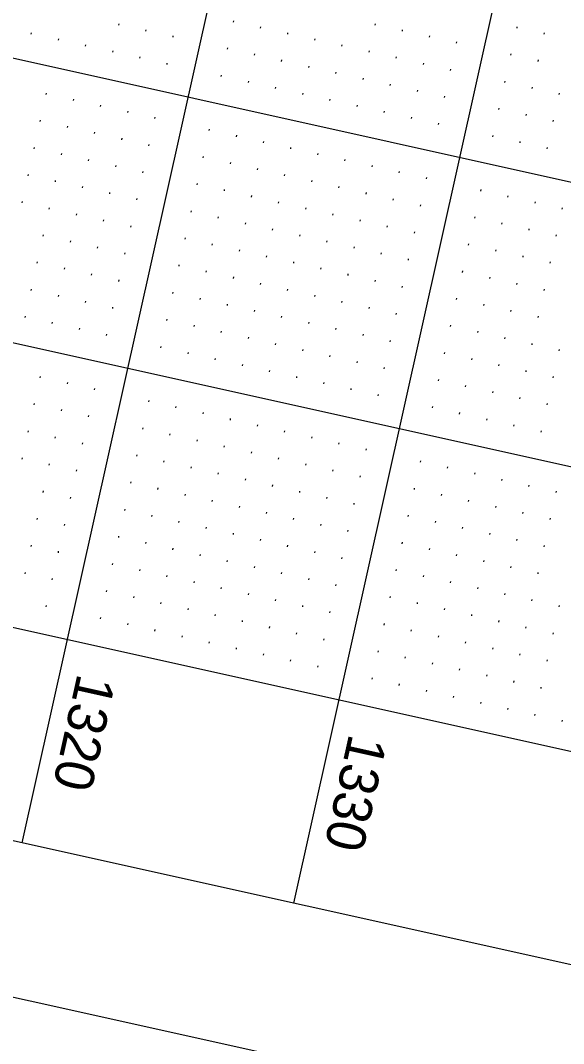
# Model space of a CAD drawing. Extents: x 2149268 to 2150830, y 142155 to 144285.
# Drawn here: x 2149718.3 to 2149815.9, y 142325.7 to 142509.8 of the extents above; entities that cross this region are included whole.
import ezdxf

# ---------------------------------------------------------------- set-up
doc = ezdxf.new("R2010")
doc.units = 0
for name, color, linetype in [('SHT_Plan_Profile_Sheet_Elev_Txt', 7, 'Continuous'), ('SHT_Plot_Shape_Half', 7, 'Continuous'), ('SHT_Profile_Grid_Major', 7, 'Continuous'), ('SHT_Profile_Grid_Minor', 7, 'Continuous'), ('SHT_Sheet_Border', 7, 'Continuous')]:
    doc.layers.add(name, color=color, linetype=linetype)

msp = doc.modelspace()

# ---------------------------------------------------------------- linework, layer by layer
at = {"layer": 'SHT_Plot_Shape_Half'}
msp.add_lwpolyline([(2150772.24, 143840.86), (2150403.25, 142181.39), (2149329.47, 142420.15), (2149698.47, 144079.62)], close=True, dxfattribs=at)
at = {"layer": 'SHT_Profile_Grid_Major'}
for p, q in [((2150060.45, 143899.25), (2149718.58, 142361.8)), ((2150109.25, 143888.4), (2149767.39, 142350.95)), ((2149504.39, 142550.29), (2149894.85, 142463.47)), ((2149493.54, 142501.48), (2149884, 142414.66))]:
    msp.add_line(p, q, dxfattribs=at)
at = {"layer": 'SHT_Profile_Grid_Minor'}
for p, q in [((2149735.98, 142509.16), (2149735.93, 142508.92)), ((2149740.86, 142508.08), (2149740.81, 142507.84)), ((2149756.59, 142509.7), (2149756.54, 142509.46)), ((2149761.47, 142508.62), (2149761.42, 142508.37)), ((2149782.08, 142509.16), (2149782.03, 142508.91)), ((2149786.96, 142508.07), (2149786.91, 142507.83)), ((2149807.57, 142508.61), (2149807.52, 142508.37)), ((2149720.26, 142507.54), (2149720.2, 142507.3)), ((2149725.14, 142506.45), (2149725.08, 142506.21)), ((2149745.74, 142506.99), (2149745.69, 142506.75)), ((2149766.35, 142507.53), (2149766.3, 142507.29)), ((2149771.23, 142506.45), (2149771.18, 142506.2)), ((2149791.84, 142506.99), (2149791.79, 142506.74)), ((2149812.45, 142507.53), (2149812.4, 142507.28)), ((2149730.02, 142505.37), (2149729.96, 142505.13)), ((2149734.9, 142504.28), (2149734.84, 142504.04)), ((2149755.51, 142504.82), (2149755.45, 142504.58)), ((2149776.12, 142505.36), (2149776.06, 142505.12)), ((2149781, 142504.28), (2149780.94, 142504.03)), ((2149796.72, 142505.9), (2149796.67, 142505.66)), ((2149739.78, 142503.2), (2149739.72, 142502.95)), ((2149760.39, 142503.74), (2149760.33, 142503.49)), ((2149765.27, 142502.65), (2149765.21, 142502.41)), ((2149785.88, 142503.19), (2149785.82, 142502.95)), ((2149806.49, 142503.73), (2149806.43, 142503.49)), ((2149811.37, 142502.65), (2149811.31, 142502.4)), ((2149744.66, 142502.11), (2149744.61, 142501.87)), ((2149770.15, 142501.57), (2149770.09, 142501.32)), ((2149790.76, 142502.11), (2149790.7, 142501.86)), ((2149795.64, 142501.02), (2149795.58, 142500.78)), ((2149754.42, 142499.94), (2149754.37, 142499.7)), ((2149759.3, 142498.86), (2149759.25, 142498.61)), ((2149775.03, 142500.48), (2149774.98, 142500.24)), ((2149779.91, 142499.4), (2149779.86, 142499.15)), ((2149805.4, 142498.85), (2149805.35, 142498.61)), ((2149764.18, 142497.77), (2149764.13, 142497.53)), ((2149784.79, 142498.31), (2149784.74, 142498.07)), ((2149789.67, 142497.23), (2149789.62, 142496.98)), ((2149810.28, 142497.77), (2149810.23, 142497.52)), ((2149722.97, 142496.69), (2149722.91, 142496.45)), ((2149727.85, 142495.61), (2149727.79, 142495.36)), ((2149769.06, 142496.69), (2149769.01, 142496.44)), ((2149773.94, 142495.6), (2149773.89, 142495.36)), ((2149794.55, 142496.14), (2149794.5, 142495.9)), ((2149815.16, 142496.68), (2149815.11, 142496.44)), ((2149732.73, 142494.52), (2149732.67, 142494.28)), ((2149737.61, 142493.44), (2149737.55, 142493.19)), ((2149778.83, 142494.52), (2149778.77, 142494.27)), ((2149783.71, 142493.43), (2149783.65, 142493.19)), ((2149804.31, 142493.97), (2149804.26, 142493.73)), ((2149721.88, 142491.81), (2149721.83, 142491.57)), ((2149742.49, 142492.35), (2149742.43, 142492.11)), ((2149788.59, 142492.35), (2149788.53, 142492.1)), ((2149809.2, 142492.89), (2149809.14, 142492.64)), ((2149814.08, 142491.8), (2149814.02, 142491.56)), ((2149726.76, 142490.73), (2149726.71, 142490.48)), ((2149731.64, 142489.64), (2149731.59, 142489.4)), ((2149752.25, 142490.18), (2149752.2, 142489.94)), ((2149793.47, 142491.26), (2149793.41, 142491.02)), ((2149736.52, 142488.56), (2149736.47, 142488.31)), ((2149757.13, 142489.1), (2149757.08, 142488.85)), ((2149762.01, 142488.01), (2149761.96, 142487.77)), ((2149803.23, 142489.09), (2149803.18, 142488.85)), ((2149808.11, 142488), (2149808.06, 142487.76)), ((2149720.8, 142486.93), (2149720.74, 142486.69)), ((2149725.68, 142485.85), (2149725.62, 142485.6)), ((2149741.4, 142487.47), (2149741.35, 142487.23)), ((2149766.89, 142486.93), (2149766.84, 142486.68)), ((2149771.77, 142485.84), (2149771.72, 142485.6)), ((2149812.99, 142486.92), (2149812.94, 142486.68)), ((2149730.56, 142484.76), (2149730.5, 142484.52)), ((2149751.17, 142485.3), (2149751.11, 142485.06)), ((2149756.05, 142484.21), (2149755.99, 142483.97)), ((2149776.65, 142484.75), (2149776.6, 142484.51)), ((2149735.44, 142483.68), (2149735.38, 142483.43)), ((2149740.32, 142482.59), (2149740.26, 142482.35)), ((2149760.93, 142483.13), (2149760.87, 142482.89)), ((2149781.54, 142483.67), (2149781.48, 142483.43)), ((2149786.42, 142482.58), (2149786.36, 142482.34)), ((2149719.71, 142482.05), (2149719.66, 142481.81)), ((2149724.59, 142480.97), (2149724.54, 142480.72)), ((2149750.08, 142480.42), (2149750.03, 142480.18)), ((2149765.81, 142482.04), (2149765.75, 142481.8)), ((2149770.69, 142480.96), (2149770.63, 142480.72)), ((2149791.3, 142481.5), (2149791.24, 142481.25)), ((2149729.47, 142479.88), (2149729.42, 142479.64)), ((2149734.35, 142478.79), (2149734.3, 142478.55)), ((2149754.96, 142479.33), (2149754.91, 142479.09)), ((2149775.57, 142479.87), (2149775.52, 142479.63)), ((2149780.45, 142478.79), (2149780.4, 142478.54)), ((2149801.06, 142479.33), (2149801, 142479.08)), ((2149718.62, 142477.17), (2149718.57, 142476.93)), ((2149739.23, 142477.71), (2149739.18, 142477.47)), ((2149759.84, 142478.25), (2149759.79, 142478)), ((2149764.72, 142477.16), (2149764.67, 142476.92)), ((2149785.33, 142477.7), (2149785.28, 142477.46)), ((2149805.94, 142478.24), (2149805.89, 142478)), ((2149810.82, 142477.16), (2149810.77, 142476.91)), ((2149723.51, 142476.08), (2149723.45, 142475.84)), ((2149728.39, 142475), (2149728.33, 142474.75)), ((2149748.99, 142475.54), (2149748.94, 142475.29)), ((2149769.6, 142476.08), (2149769.55, 142475.83)), ((2149774.48, 142474.99), (2149774.43, 142474.75)), ((2149790.21, 142476.62), (2149790.16, 142476.37)), ((2149815.7, 142476.07), (2149815.65, 142475.83)), ((2149733.27, 142473.91), (2149733.21, 142473.67)), ((2149753.88, 142474.45), (2149753.82, 142474.21)), ((2149758.76, 142473.37), (2149758.7, 142473.12)), ((2149779.36, 142473.91), (2149779.31, 142473.66)), ((2149799.97, 142474.45), (2149799.92, 142474.2)), ((2149804.85, 142473.36), (2149804.8, 142473.12)), ((2149722.42, 142471.2), (2149722.37, 142470.96)), ((2149738.15, 142472.83), (2149738.09, 142472.58)), ((2149763.64, 142472.28), (2149763.58, 142472.04)), ((2149768.52, 142471.2), (2149768.46, 142470.95)), ((2149784.25, 142472.82), (2149784.19, 142472.58)), ((2149789.13, 142471.74), (2149789.07, 142471.49)), ((2149809.73, 142472.28), (2149809.68, 142472.03)), ((2149814.62, 142471.19), (2149814.56, 142470.95)), ((2149727.3, 142470.12), (2149727.25, 142469.87)), ((2149747.91, 142470.66), (2149747.86, 142470.41)), ((2149752.79, 142469.57), (2149752.74, 142469.33)), ((2149773.4, 142470.11), (2149773.34, 142469.87)), ((2149798.89, 142469.57), (2149798.83, 142469.32)), ((2149732.18, 142469.03), (2149732.13, 142468.79)), ((2149737.06, 142467.95), (2149737.01, 142467.7)), ((2149757.67, 142468.49), (2149757.62, 142468.24)), ((2149778.28, 142469.03), (2149778.23, 142468.78)), ((2149783.16, 142467.94), (2149783.11, 142467.7)), ((2149803.77, 142468.48), (2149803.71, 142468.24)), ((2149721.34, 142466.32), (2149721.28, 142466.08)), ((2149746.82, 142465.78), (2149746.77, 142465.53)), ((2149762.55, 142467.4), (2149762.5, 142467.16)), ((2149767.43, 142466.32), (2149767.38, 142466.07)), ((2149788.04, 142466.86), (2149787.99, 142466.61)), ((2149808.65, 142467.4), (2149808.6, 142467.15)), ((2149813.53, 142466.31), (2149813.48, 142466.07)), ((2149726.22, 142465.24), (2149726.16, 142464.99)), ((2149731.1, 142464.15), (2149731.04, 142463.91)), ((2149751.71, 142464.69), (2149751.65, 142464.45)), ((2149772.31, 142465.23), (2149772.26, 142464.99)), ((2149777.19, 142464.15), (2149777.14, 142463.9)), ((2149797.8, 142464.69), (2149797.75, 142464.44)), ((2149735.98, 142463.07), (2149735.92, 142462.82)), ((2149756.59, 142463.61), (2149756.53, 142463.36)), ((2149761.47, 142462.52), (2149761.41, 142462.28)), ((2149782.08, 142463.06), (2149782.02, 142462.82)), ((2149786.96, 142461.98), (2149786.9, 142461.73)), ((2149802.68, 142463.6), (2149802.63, 142463.36)), ((2149807.56, 142462.52), (2149807.51, 142462.27)), ((2149720.25, 142461.44), (2149720.2, 142461.2)), ((2149725.13, 142460.36), (2149725.08, 142460.11)), ((2149745.74, 142460.9), (2149745.68, 142460.65)), ((2149766.35, 142461.44), (2149766.29, 142461.19)), ((2149771.23, 142460.35), (2149771.17, 142460.11)), ((2149812.45, 142461.43), (2149812.39, 142461.19)), ((2149730.01, 142459.27), (2149729.96, 142459.03)), ((2149750.62, 142459.81), (2149750.57, 142459.57)), ((2149755.5, 142458.73), (2149755.45, 142458.48)), ((2149776.11, 142459.27), (2149776.05, 142459.02)), ((2149796.72, 142459.81), (2149796.66, 142459.56)), ((2149801.6, 142458.72), (2149801.54, 142458.48)), ((2149719.16, 142456.56), (2149719.11, 142456.32)), ((2149734.89, 142458.19), (2149734.84, 142457.94)), ((2149760.38, 142457.64), (2149760.33, 142457.4)), ((2149765.26, 142456.56), (2149765.21, 142456.31)), ((2149780.99, 142458.18), (2149780.94, 142457.94)), ((2149785.87, 142457.09), (2149785.82, 142456.85)), ((2149806.48, 142457.63), (2149806.42, 142457.39)), ((2149811.36, 142456.55), (2149811.31, 142456.31)), ((2149724.05, 142455.48), (2149723.99, 142455.23)), ((2149744.65, 142456.02), (2149744.6, 142455.77)), ((2149749.53, 142454.93), (2149749.48, 142454.69)), ((2149770.14, 142455.47), (2149770.09, 142455.23)), ((2149795.63, 142454.92), (2149795.58, 142454.68)), ((2149728.93, 142454.39), (2149728.87, 142454.15)), ((2149733.81, 142453.31), (2149733.75, 142453.06)), ((2149754.42, 142453.84), (2149754.36, 142453.6)), ((2149759.3, 142452.76), (2149759.24, 142452.52)), ((2149775.02, 142454.38), (2149774.97, 142454.14)), ((2149779.9, 142453.3), (2149779.85, 142453.06)), ((2149800.51, 142453.84), (2149800.46, 142453.6)), ((2149805.39, 142452.75), (2149805.34, 142452.51)), ((2149743.57, 142451.13), (2149743.51, 142450.89)), ((2149764.18, 142451.67), (2149764.12, 142451.43)), ((2149784.79, 142452.21), (2149784.73, 142451.97)), ((2149810.27, 142451.67), (2149810.22, 142451.42)), ((2149748.45, 142450.05), (2149748.4, 142449.81)), ((2149769.06, 142450.59), (2149769, 142450.35)), ((2149773.94, 142449.5), (2149773.88, 142449.26)), ((2149794.55, 142450.04), (2149794.49, 142449.8)), ((2149815.16, 142450.58), (2149815.1, 142450.34)), ((2149753.33, 142448.96), (2149753.28, 142448.72)), ((2149758.21, 142447.88), (2149758.16, 142447.63)), ((2149778.82, 142448.42), (2149778.77, 142448.17)), ((2149783.7, 142447.33), (2149783.65, 142447.09)), ((2149799.43, 142448.96), (2149799.37, 142448.71)), ((2149804.31, 142447.87), (2149804.25, 142447.63)), ((2149721.87, 142445.71), (2149721.82, 142445.47)), ((2149763.09, 142446.79), (2149763.04, 142446.55)), ((2149767.97, 142445.71), (2149767.92, 142445.46)), ((2149809.19, 142446.79), (2149809.14, 142446.54)), ((2149814.07, 142445.7), (2149814.02, 142445.46)), ((2149726.76, 142444.63), (2149726.7, 142444.38)), ((2149731.64, 142443.54), (2149731.58, 142443.3)), ((2149772.85, 142444.62), (2149772.8, 142444.38)), ((2149777.73, 142443.54), (2149777.68, 142443.29)), ((2149793.46, 142445.16), (2149793.41, 142444.92)), ((2149798.34, 142444.08), (2149798.29, 142443.83)), ((2149782.61, 142442.45), (2149782.56, 142442.21)), ((2149803.22, 142442.99), (2149803.17, 142442.75)), ((2149808.1, 142441.91), (2149808.05, 142441.66)), ((2149720.79, 142440.83), (2149720.74, 142440.59)), ((2149741.4, 142441.37), (2149741.34, 142441.13)), ((2149746.28, 142440.29), (2149746.22, 142440.04)), ((2149792.38, 142440.28), (2149792.32, 142440.04)), ((2149812.98, 142440.82), (2149812.93, 142440.58)), ((2149725.67, 142439.75), (2149725.62, 142439.5)), ((2149730.55, 142438.66), (2149730.5, 142438.42)), ((2149751.16, 142439.2), (2149751.11, 142438.96)), ((2149756.04, 142438.12), (2149755.99, 142437.87)), ((2149797.26, 142439.2), (2149797.2, 142438.95)), ((2149802.14, 142438.11), (2149802.08, 142437.87)), ((2149740.31, 142436.49), (2149740.26, 142436.25)), ((2149760.92, 142437.03), (2149760.87, 142436.79)), ((2149807.02, 142437.03), (2149806.96, 142436.78)), ((2149719.7, 142435.95), (2149719.65, 142435.71)), ((2149724.58, 142434.87), (2149724.53, 142434.62)), ((2149745.19, 142435.41), (2149745.14, 142435.16)), ((2149750.07, 142434.32), (2149750.02, 142434.08)), ((2149765.8, 142435.95), (2149765.75, 142435.7)), ((2149770.68, 142434.86), (2149770.63, 142434.62)), ((2149811.9, 142435.94), (2149811.85, 142435.7)), ((2149729.47, 142433.78), (2149729.41, 142433.54)), ((2149754.96, 142433.24), (2149754.9, 142432.99)), ((2149775.56, 142433.78), (2149775.51, 142433.53)), ((2149780.44, 142432.69), (2149780.39, 142432.45)), ((2149718.62, 142431.07), (2149718.56, 142430.83)), ((2149739.23, 142431.61), (2149739.17, 142431.37)), ((2149759.84, 142432.15), (2149759.78, 142431.91)), ((2149764.72, 142431.07), (2149764.66, 142430.82)), ((2149723.5, 142429.99), (2149723.45, 142429.74)), ((2149728.38, 142428.9), (2149728.33, 142428.66)), ((2149744.11, 142430.53), (2149744.05, 142430.28)), ((2149748.99, 142429.44), (2149748.93, 142429.2)), ((2149769.6, 142429.98), (2149769.54, 142429.74)), ((2149774.48, 142428.9), (2149774.42, 142428.65)), ((2149790.21, 142430.52), (2149790.15, 142430.28)), ((2149795.09, 142429.44), (2149795.03, 142429.19)), ((2149753.87, 142428.36), (2149753.82, 142428.11)), ((2149758.75, 142427.27), (2149758.7, 142427.03)), ((2149779.36, 142427.81), (2149779.3, 142427.57)), ((2149799.97, 142428.35), (2149799.91, 142428.11)), ((2149804.85, 142427.26), (2149804.79, 142427.02)), ((2149722.41, 142425.11), (2149722.36, 142424.86)), ((2149738.14, 142426.73), (2149738.09, 142426.49)), ((2149743.02, 142425.65), (2149742.97, 142425.4)), ((2149763.63, 142426.19), (2149763.58, 142425.94)), ((2149768.51, 142425.1), (2149768.46, 142424.86)), ((2149789.12, 142425.64), (2149789.07, 142425.4)), ((2149809.73, 142426.18), (2149809.67, 142425.94)), ((2149727.3, 142424.02), (2149727.24, 142423.78)), ((2149747.9, 142424.56), (2149747.85, 142424.32)), ((2149752.78, 142423.47), (2149752.73, 142423.23)), ((2149773.39, 142424.01), (2149773.34, 142423.77)), ((2149794, 142424.55), (2149793.95, 142424.31)), ((2149798.88, 142423.47), (2149798.83, 142423.22)), ((2149814.61, 142425.09), (2149814.56, 142424.85)), ((2149737.06, 142421.85), (2149737, 142421.61)), ((2149757.67, 142422.39), (2149757.61, 142422.15)), ((2149778.27, 142422.93), (2149778.22, 142422.69)), ((2149803.76, 142422.38), (2149803.71, 142422.14)), ((2149721.33, 142420.23), (2149721.27, 142419.98)), ((2149741.94, 142420.76), (2149741.88, 142420.52)), ((2149746.82, 142419.68), (2149746.76, 142419.44)), ((2149762.55, 142421.3), (2149762.49, 142421.06)), ((2149767.43, 142420.22), (2149767.37, 142419.98)), ((2149788.04, 142420.76), (2149787.98, 142420.51)), ((2149792.92, 142419.67), (2149792.86, 142419.43)), ((2149808.64, 142421.3), (2149808.59, 142421.05)), ((2149813.52, 142420.21), (2149813.47, 142419.97)), ((2149726.21, 142419.14), (2149726.16, 142418.9)), ((2149751.7, 142418.59), (2149751.64, 142418.35)), ((2149772.31, 142419.13), (2149772.25, 142418.89)), ((2149777.19, 142418.05), (2149777.13, 142417.8)), ((2149797.8, 142418.59), (2149797.74, 142418.34)), ((2149735.97, 142416.97), (2149735.92, 142416.73)), ((2149756.58, 142417.51), (2149756.53, 142417.26)), ((2149761.46, 142416.42), (2149761.41, 142416.18)), ((2149802.68, 142417.5), (2149802.62, 142417.26)), ((2149807.56, 142416.42), (2149807.5, 142416.17)), ((2149720.24, 142415.34), (2149720.19, 142415.1)), ((2149725.12, 142414.26), (2149725.07, 142414.01)), ((2149740.85, 142415.88), (2149740.8, 142415.64)), ((2149745.73, 142414.8), (2149745.68, 142414.55)), ((2149766.34, 142415.34), (2149766.29, 142415.09)), ((2149771.22, 142414.25), (2149771.17, 142414.01)), ((2149786.95, 142415.88), (2149786.9, 142415.63)), ((2149791.83, 142414.79), (2149791.78, 142414.55)), ((2149812.44, 142415.33), (2149812.39, 142415.09)), ((2149750.61, 142413.71), (2149750.56, 142413.47)), ((2149755.49, 142412.63), (2149755.44, 142412.38)), ((2149776.1, 142413.17), (2149776.05, 142412.92)), ((2149796.71, 142413.71), (2149796.66, 142413.46)), ((2149801.59, 142412.62), (2149801.54, 142412.38)), ((2149719.16, 142410.46), (2149719.1, 142410.22)), ((2149734.89, 142412.09), (2149734.83, 142411.84)), ((2149739.77, 142411), (2149739.71, 142410.76)), ((2149760.38, 142411.54), (2149760.32, 142411.3)), ((2149765.26, 142410.46), (2149765.2, 142410.21)), ((2149785.86, 142411), (2149785.81, 142410.75)), ((2149806.47, 142411.54), (2149806.42, 142411.29)), ((2149811.35, 142410.45), (2149811.3, 142410.21)), ((2149724.04, 142409.38), (2149723.99, 142409.13)), ((2149744.65, 142409.92), (2149744.59, 142409.67)), ((2149749.53, 142408.83), (2149749.47, 142408.59)), ((2149770.14, 142409.37), (2149770.08, 142409.13)), ((2149790.75, 142409.91), (2149790.69, 142409.67)), ((2149795.63, 142408.83), (2149795.57, 142408.58)), ((2149733.8, 142407.21), (2149733.75, 142406.96)), ((2149754.41, 142407.75), (2149754.36, 142407.5)), ((2149775.02, 142408.29), (2149774.96, 142408.04)), ((2149800.51, 142407.74), (2149800.45, 142407.5)), ((2149738.68, 142406.12), (2149738.63, 142405.88)), ((2149743.56, 142405.04), (2149743.51, 142404.79)), ((2149759.29, 142406.66), (2149759.24, 142406.42)), ((2149764.17, 142405.58), (2149764.12, 142405.33)), ((2149784.78, 142406.12), (2149784.73, 142405.87)), ((2149789.66, 142405.03), (2149789.61, 142404.79)), ((2149805.39, 142406.66), (2149805.33, 142406.41)), ((2149810.27, 142405.57), (2149810.21, 142405.33)), ((2149722.95, 142404.5), (2149722.9, 142404.25)), ((2149748.44, 142403.95), (2149748.39, 142403.71)), ((2149769.05, 142404.49), (2149769, 142404.25)), ((2149773.93, 142403.41), (2149773.88, 142403.16)), ((2149794.54, 142403.95), (2149794.49, 142403.7)), ((2149815.15, 142404.49), (2149815.1, 142404.24)), ((2149732.72, 142402.33), (2149732.66, 142402.08)), ((2149737.6, 142401.24), (2149737.54, 142401)), ((2149753.32, 142402.87), (2149753.27, 142402.62)), ((2149758.2, 142401.78), (2149758.15, 142401.54)), ((2149783.69, 142401.24), (2149783.64, 142400.99)), ((2149799.42, 142402.86), (2149799.37, 142402.62)), ((2149804.3, 142401.78), (2149804.25, 142401.53)), ((2149742.48, 142400.16), (2149742.42, 142399.91)), ((2149763.09, 142400.7), (2149763.03, 142400.45)), ((2149767.97, 142399.61), (2149767.91, 142399.37)), ((2149788.58, 142400.15), (2149788.52, 142399.91)), ((2149809.18, 142400.69), (2149809.13, 142400.45)), ((2149814.06, 142399.6), (2149814.01, 142399.36)), ((2149747.36, 142399.07), (2149747.3, 142398.83)), ((2149752.24, 142397.99), (2149752.18, 142397.74)), ((2149772.85, 142398.53), (2149772.79, 142398.28)), ((2149793.46, 142399.07), (2149793.4, 142398.82)), ((2149798.34, 142397.98), (2149798.28, 142397.74)), ((2149757.12, 142396.9), (2149757.07, 142396.66)), ((2149762, 142395.82), (2149761.95, 142395.57)), ((2149782.61, 142396.35), (2149782.55, 142396.11)), ((2149803.22, 142396.89), (2149803.16, 142396.65)), ((2149808.1, 142395.81), (2149808.04, 142395.57)), ((2149766.88, 142394.73), (2149766.83, 142394.49)), ((2149787.49, 142395.27), (2149787.44, 142395.03)), ((2149792.37, 142394.18), (2149792.32, 142393.94)), ((2149812.98, 142394.72), (2149812.92, 142394.48)), ((2149771.76, 142393.64), (2149771.71, 142393.4)), ((2149797.25, 142393.1), (2149797.2, 142392.85)), ((2149802.13, 142392.01), (2149802.08, 142391.77)), ((2149781.52, 142391.47), (2149781.47, 142391.23)), ((2149786.4, 142390.39), (2149786.35, 142390.14)), ((2149807.01, 142390.93), (2149806.96, 142390.68)), ((2149791.29, 142389.3), (2149791.23, 142389.06)), ((2149811.89, 142389.84), (2149811.84, 142389.6)), ((2149796.17, 142388.22), (2149796.11, 142387.97)), ((2149801.05, 142387.13), (2149800.99, 142386.89)), ((2149805.93, 142386.05), (2149805.87, 142385.8)), ((2149810.81, 142384.96), (2149810.75, 142384.72)), ((2149815.69, 142383.88), (2149815.63, 142383.63))]:
    msp.add_line(p, q, dxfattribs=at)
at = {"layer": 'SHT_Sheet_Border'}
msp.add_line((2149409.47, 142468.95), (2149873.15, 142365.85), dxfattribs=at)
msp.add_lwpolyline([(2150726.67, 143751.11), (2150384.81, 142213.66), (2149359.84, 142441.57), (2149701.71, 143979.02)], close=True, dxfattribs=at)

# ---------------------------------------------------------------- texts
at = {"layer": 'SHT_Plan_Profile_Sheet_Elev_Txt'}
for s, p in [('1320', (2149728.63, 142392.46)), ('1330', (2149777.44, 142381.61))]:
    msp.add_text(s, height=7, rotation=257.4638, dxfattribs=at).set_placement(p)

doc.saveas('drawing.dxf')
